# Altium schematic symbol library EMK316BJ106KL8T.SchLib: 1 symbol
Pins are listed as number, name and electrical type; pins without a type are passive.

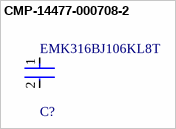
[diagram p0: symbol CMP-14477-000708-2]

## CMP-14477-000708-2
designator C?, comment EMK316BJ106KL8T
None
footprint FP-1206-L_3_2_0_15-W_1_6-IPC_C
footprint FP-1206-L_3_2_0_15-W_1_6-IPC_A
footprint FP-1206-L_3_2_0_15-W_1_6-IPC_B
footprint FP-1206-L_3_2_0_15-W_1_6-MFG
pins: 1, 2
